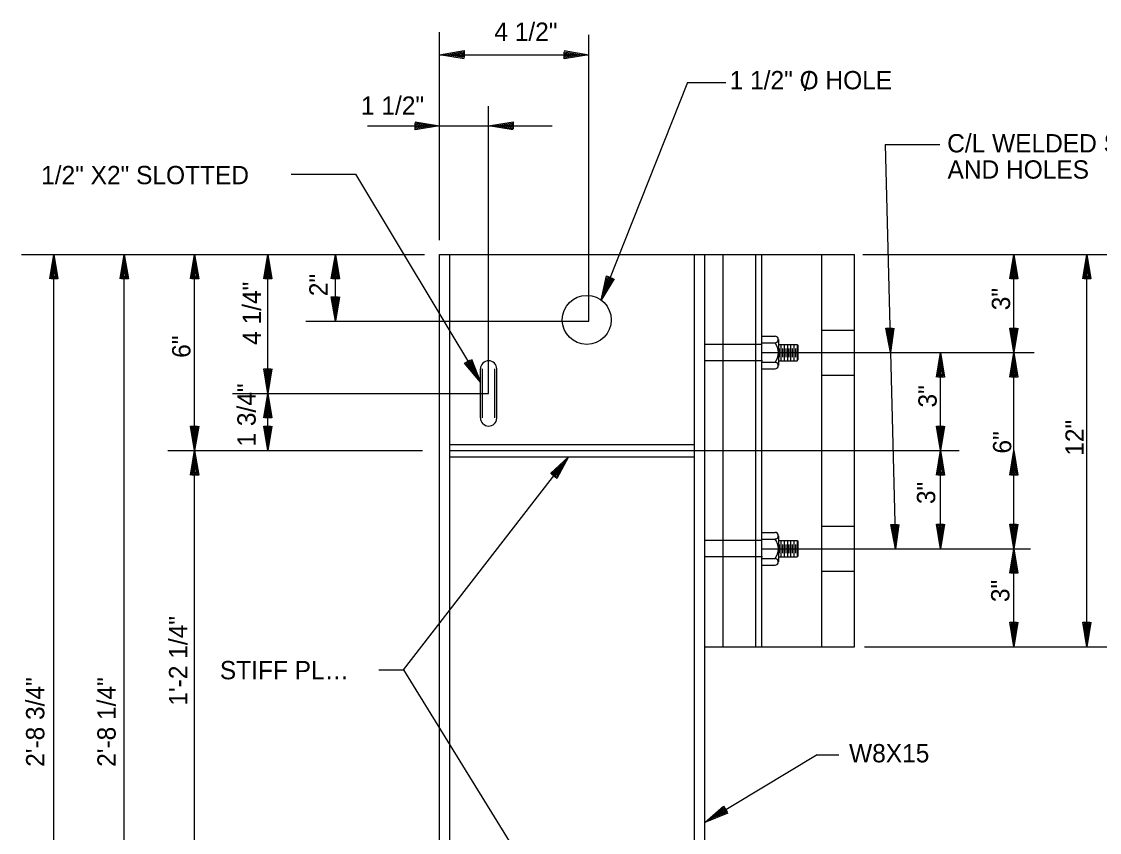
# Model space of a CAD drawing. Extents: x 0.1 to 13.5, y 0.1 to 9.5.
# Drawn here: x 9.259 to 12.007, y 5.002 to 7.069 of the extents above; entities that cross this region are included whole.
import ezdxf

# ---------------------------------------------------------------- set-up
doc = ezdxf.new("R2010")
doc.units = 0
for name, color, linetype in [('Level 13', 7, 'Continuous'), ('Level 25', 7, 'Continuous'), ('Level 50', 7, 'Continuous')]:
    doc.layers.add(name, color=color, linetype=linetype)

msp = doc.modelspace()

# ---------------------------------------------------------------- linework, layer by layer
at = {"layer": 'Level 13'}
for p, q in [((11.1464, 6.2666), (11.1797, 6.2666)), ((11.1469, 6.2457), (11.0006, 6.2457)), ((11.1464, 6.2494), (11.1797, 6.2494)), ((11.1881, 6.2581), (11.1881, 6.1916)), ((11.1881, 6.2457), (11.2359, 6.2457)), ((11.1944, 6.2457), (11.1944, 6.2041)), ((11.2027, 6.2457), (11.2027, 6.2041)), ((11.211, 6.2457), (11.211, 6.2041)), ((11.2194, 6.2457), (11.2194, 6.2041)), ((11.2277, 6.2457), (11.2277, 6.2041)), ((11.2359, 6.2457), (11.2381, 6.2435)), ((11.236, 6.2457), (11.236, 6.2041)), ((11.2381, 6.2435), (11.2381, 6.2062)), ((11.1902, 6.2353), (11.1902, 6.2135)), ((11.1985, 6.2353), (11.1985, 6.2135)), ((11.2069, 6.2353), (11.2069, 6.2135)), ((11.2152, 6.2353), (11.2152, 6.2135)), ((11.2235, 6.2353), (11.2235, 6.2135)), ((11.2319, 6.2353), (11.2319, 6.2135)), ((11.1476, 6.2041), (11.0006, 6.2041)), ((11.1464, 6.2001), (11.1797, 6.2001)), ((11.1464, 6.1832), (11.1797, 6.1832)), ((11.1881, 6.2041), (11.2358, 6.2041)), ((11.2358, 6.2041), (11.2381, 6.2062)), ((11.1469, 5.7457), (11.0006, 5.7457)), ((11.1464, 5.7666), (11.1797, 5.7666)), ((11.1464, 5.7494), (11.1797, 5.7494)), ((11.1881, 5.7581), (11.1881, 5.6916)), ((11.1881, 5.7457), (11.2359, 5.7457)), ((11.1944, 5.7457), (11.1944, 5.7041)), ((11.2027, 5.7457), (11.2027, 5.7041)), ((11.211, 5.7457), (11.211, 5.7041)), ((11.2194, 5.7457), (11.2194, 5.7041)), ((11.2277, 5.7457), (11.2277, 5.7041)), ((11.2359, 5.7457), (11.2381, 5.7435)), ((11.236, 5.7457), (11.236, 5.7041)), ((11.2381, 5.7435), (11.2381, 5.7062)), ((11.1902, 5.7353), (11.1902, 5.7135)), ((11.1985, 5.7353), (11.1985, 5.7135)), ((11.2069, 5.7353), (11.2069, 5.7135)), ((11.2152, 5.7353), (11.2152, 5.7135)), ((11.2235, 5.7353), (11.2235, 5.7135)), ((11.2319, 5.7353), (11.2319, 5.7135)), ((11.1476, 5.7041), (11.0006, 5.7041)), ((11.1464, 5.7001), (11.1797, 5.7001)), ((11.1881, 5.7041), (11.2358, 5.7041)), ((11.2358, 5.7041), (11.2381, 5.7062)), ((11.1464, 5.6832), (11.1797, 5.6832))]:
    msp.add_line(p, q, dxfattribs=at)
for centre, radius, start, end in [((11.1796, 6.2581), 0.00844, 270.5659, 89.4341), ((11.1475, 6.2247), 0.0406, 322.4343, 37.5657), ((11.1796, 6.1917), 0.00843, 270.4975, 89.5025), ((11.1796, 5.7581), 0.00844, 270.5659, 89.4341), ((11.1475, 5.7247), 0.0406, 322.4343, 37.5657), ((11.1796, 5.6917), 0.00843, 270.4975, 89.5025)]:
    msp.add_arc(centre, radius, start, end, dxfattribs=at)
at = {"layer": 'Level 25'}
for p, q in [((10.3247, 6.5117), (10.3247, 7.0417)), ((10.7048, 6.3047), (10.7048, 7.0348)), ((10.3247, 6.9843), (10.7048, 6.9843)), ((10.9565, 6.9132), (10.7368, 6.3586)), ((10.9565, 6.9132), (11.0544, 6.9132)), ((10.4497, 6.4749), (10.4497, 6.8533)), ((10.1408, 6.8029), (10.3247, 6.8029)), ((10.3247, 6.8029), (10.4497, 6.8029)), ((10.4497, 6.8029), (10.6115, 6.8029)), ((11.4602, 6.755), (11.6001, 6.755)), ((11.4602, 6.755), (11.4737, 6.2249)), ((9.9466, 6.6798), (10.1099, 6.6798)), ((10.1099, 6.6798), (10.4289, 6.1497)), ((9.2591, 6.4749), (10.2858, 6.4749)), ((9.3416, 3.7457), (9.3416, 6.4749)), ((9.5209, 3.7874), (9.5209, 6.4749)), ((9.7003, 5.9749), (9.7003, 6.4749)), ((9.8869, 6.1207), (9.8869, 6.4749)), ((10.059, 6.3047), (10.059, 6.4749)), ((10.3247, 6.4749), (11.382, 6.4749)), ((10.3247, 6.4749), (10.3247, 6.4749)), ((10.3247, 3.7457), (10.3247, 6.4749)), ((10.351, 3.8291), (10.351, 6.4749)), ((10.4497, 6.1207), (10.4497, 6.4749)), ((10.9743, 3.8291), (10.9743, 6.4749)), ((11.0006, 3.7457), (11.0006, 6.4749)), ((11.0474, 5.4749), (11.0474, 6.4749)), ((11.1308, 5.4749), (11.1308, 6.4749)), ((11.1464, 5.4749), (11.1464, 6.4749)), ((11.2987, 5.4749), (11.2987, 6.4749)), ((11.382, 5.4749), (11.382, 6.4749)), ((11.4035, 6.4749), (12.0554, 6.4749)), ((11.7881, 6.2249), (11.7881, 6.4749)), ((11.9747, 5.4749), (11.9747, 6.4749)), ((9.9838, 6.3047), (10.7048, 6.3047)), ((11.1464, 6.1832), (11.1464, 6.2666)), ((11.2987, 6.2822), (11.382, 6.2822)), ((11.1464, 6.2249), (11.84, 6.2249)), ((11.4737, 6.2249), (11.4864, 5.7243)), ((11.6016, 5.9749), (11.6016, 6.2249)), ((11.7881, 5.7249), (11.7881, 6.2249)), ((10.4289, 6.0582), (10.4289, 6.1832)), ((10.4341, 6.0582), (10.4341, 6.1832)), ((10.4654, 6.0582), (10.4654, 6.1832)), ((10.4706, 6.0582), (10.4706, 6.1832)), ((11.2987, 6.1676), (11.382, 6.1676)), ((9.7972, 6.1207), (10.4497, 6.1207)), ((9.8869, 5.9749), (9.8869, 6.1207)), ((10.351, 5.9905), (10.9743, 5.9905)), ((9.6322, 5.9749), (10.2811, 5.9749)), ((9.7003, 4.7874), (9.7003, 5.9749)), ((10.351, 5.9749), (10.9743, 5.9749)), ((10.9743, 5.9749), (11.6492, 5.9749)), ((11.6016, 5.7249), (11.6016, 5.9749)), ((10.2325, 5.4159), (10.6535, 5.9593)), ((10.351, 5.9593), (10.9743, 5.9593)), ((11.2987, 5.7822), (11.382, 5.7822)), ((11.1464, 5.6832), (11.1464, 5.7666)), ((11.1464, 5.7249), (11.8311, 5.7249)), ((11.7881, 5.4749), (11.7881, 5.7249)), ((11.2987, 5.6676), (11.382, 5.6676)), ((11.0006, 5.4749), (11.382, 5.4749)), ((11.4081, 5.4749), (12.0554, 5.4749)), ((10.1696, 5.4159), (10.2325, 5.4159)), ((10.2325, 5.4159), (10.6112, 4.803)), ((11.2871, 5.199), (11.0006, 5.0273)), ((11.2871, 5.199), (11.3424, 5.199))]:
    msp.add_line(p, q, dxfattribs=at)
msp.add_circle((10.6997, 6.3082), 0.0625, dxfattribs=at)
for centre, start, end in [((10.4497, 6.1832), 0, 180), ((10.4497, 6.0582), 180, 357.4819)]:
    msp.add_arc(centre, 0.0208, start, end, dxfattribs=at)
at = {"layer": 'Level 50'}
for p, q in [((10.3247, 6.9843), (10.3247, 6.9843)), ((10.3421, 6.9843), (10.3421, 6.9843)), ((10.6875, 6.9843), (10.6875, 6.9843)), ((10.7048, 6.9843), (10.7048, 6.9843)), ((10.3074, 6.8029), (10.3074, 6.8029)), ((10.3247, 6.8029), (10.3247, 6.8029)), ((10.4497, 6.8029), (10.4497, 6.8029)), ((10.4671, 6.8029), (10.4671, 6.8029)), ((9.3416, 6.4749), (9.3416, 6.4749)), ((9.3416, 6.4576), (9.3416, 6.4576)), ((9.5209, 6.4749), (9.5209, 6.4749)), ((9.5209, 6.4576), (9.5209, 6.4576)), ((9.7003, 6.4749), (9.7003, 6.4749)), ((9.7003, 6.4576), (9.7003, 6.4576)), ((9.8869, 6.4749), (9.8869, 6.4749)), ((9.8869, 6.4576), (9.8869, 6.4576)), ((10.059, 6.4749), (10.059, 6.4749)), ((10.059, 6.4576), (10.059, 6.4576)), ((11.7881, 6.4749), (11.7881, 6.4749)), ((11.7881, 6.4576), (11.7881, 6.4576)), ((11.9747, 6.4749), (11.9747, 6.4749)), ((11.9747, 6.4576), (11.9747, 6.4576)), ((10.7432, 6.3747), (10.7432, 6.3747)), ((10.7368, 6.3586), (10.7368, 6.3586)), ((10.059, 6.322), (10.059, 6.322)), ((10.059, 6.3047), (10.059, 6.3047)), ((11.4733, 6.2422), (11.4733, 6.2422)), ((11.7881, 6.2422), (11.7881, 6.2422)), ((11.4737, 6.2249), (11.4737, 6.2249)), ((11.6016, 6.2249), (11.6016, 6.2249)), ((11.7881, 6.2249), (11.7881, 6.2249)), ((11.7881, 6.2249), (11.7881, 6.2249)), ((11.6016, 6.2076), (11.6016, 6.2076)), ((11.7881, 6.2076), (11.7881, 6.2076)), ((10.42, 6.1645), (10.42, 6.1645)), ((9.8869, 6.1381), (9.8869, 6.1381)), ((10.4289, 6.1497), (10.4289, 6.1497)), ((9.8869, 6.1207), (9.8869, 6.1207)), ((9.8869, 6.1207), (9.8869, 6.1207)), ((9.8869, 6.1034), (9.8869, 6.1034)), ((9.7003, 5.9922), (9.7003, 5.9922)), ((9.8869, 5.9922), (9.8869, 5.9922)), ((11.6016, 5.9922), (11.6016, 5.9922)), ((9.7003, 5.9749), (9.7003, 5.9749)), ((9.7003, 5.9749), (9.7003, 5.9749)), ((9.8869, 5.9749), (9.8869, 5.9749)), ((11.6016, 5.9749), (11.6016, 5.9749)), ((11.6016, 5.9749), (11.6016, 5.9749)), ((11.7881, 5.9749), (11.7881, 5.9749)), ((9.7003, 5.9576), (9.7003, 5.9576)), ((10.6428, 5.9456), (10.6428, 5.9456)), ((10.6428, 5.9456), (10.6428, 5.9456)), ((10.6535, 5.9593), (10.6535, 5.9593)), ((10.6535, 5.9593), (10.6535, 5.9593)), ((11.6016, 5.9576), (11.6016, 5.9576)), ((11.7881, 5.9576), (11.7881, 5.9576)), ((11.6016, 5.7422), (11.6016, 5.7422)), ((11.7881, 5.7422), (11.7881, 5.7422)), ((11.486, 5.7416), (11.486, 5.7416)), ((11.4864, 5.7243), (11.4864, 5.7243)), ((11.6016, 5.7249), (11.6016, 5.7249)), ((11.7881, 5.7249), (11.7881, 5.7249)), ((11.7881, 5.7249), (11.7881, 5.7249)), ((11.7881, 5.7076), (11.7881, 5.7076)), ((11.7881, 5.4922), (11.7881, 5.4922)), ((11.7881, 5.4749), (11.7881, 5.4749)), ((11.9747, 5.4922), (11.9747, 5.4922)), ((11.9747, 5.4749), (11.9747, 5.4749)), ((11.0154, 5.0362), (11.0154, 5.0362)), ((11.0006, 5.0273), (11.0006, 5.0273))]:
    msp.add_line(p, q, dxfattribs=at)
for points in [[(10.3871, 6.974), (10.3247, 6.9843), (10.3871, 6.9946), (10.3871, 6.977), (10.3421, 6.9843), (10.3844, 6.9913), (10.3844, 6.98), (10.3587, 6.9843), (10.3817, 6.988), (10.3817, 6.9833), (10.3761, 6.9843)], [(10.6425, 6.9946), (10.7048, 6.9843), (10.6425, 6.974), (10.6425, 6.9916), (10.6875, 6.9843), (10.6451, 6.9773), (10.6451, 6.9886), (10.6708, 6.9843), (10.6478, 6.9806), (10.6478, 6.9853), (10.6535, 6.9843)], [(10.2624, 6.8132), (10.3247, 6.8029), (10.2624, 6.7925), (10.2624, 6.8102), (10.3074, 6.8029), (10.2651, 6.7959), (10.2651, 6.8072), (10.2907, 6.8029), (10.2677, 6.7992), (10.2677, 6.8039), (10.2734, 6.8029)], [(10.5121, 6.7925), (10.4497, 6.8029), (10.5121, 6.8132), (10.5121, 6.7955), (10.4671, 6.8029), (10.5094, 6.8099), (10.5094, 6.7985), (10.4837, 6.8029), (10.5067, 6.8065), (10.5067, 6.8019), (10.5011, 6.8029)], [(9.3313, 6.4126), (9.3416, 6.4749), (9.3519, 6.4126), (9.3343, 6.4126), (9.3416, 6.4576), (9.3486, 6.4152), (9.3373, 6.4152), (9.3416, 6.4409), (9.3453, 6.4179), (9.3406, 6.4179), (9.3416, 6.4236)], [(9.5106, 6.4126), (9.5209, 6.4749), (9.5313, 6.4126), (9.5136, 6.4126), (9.5209, 6.4576), (9.5279, 6.4152), (9.5166, 6.4152), (9.5209, 6.4409), (9.5246, 6.4179), (9.5199, 6.4179), (9.5209, 6.4236)], [(9.69, 6.4126), (9.7003, 6.4749), (9.7106, 6.4126), (9.693, 6.4126), (9.7003, 6.4576), (9.7073, 6.4152), (9.696, 6.4152), (9.7003, 6.4409), (9.704, 6.4179), (9.6993, 6.4179), (9.7003, 6.4236)], [(9.8765, 6.4126), (9.8869, 6.4749), (9.8972, 6.4126), (9.8795, 6.4126), (9.8869, 6.4576), (9.8939, 6.4152), (9.8825, 6.4152), (9.8869, 6.4409), (9.8905, 6.4179), (9.8859, 6.4179), (9.8869, 6.4236)], [(10.0487, 6.4126), (10.059, 6.4749), (10.0694, 6.4126), (10.0517, 6.4126), (10.059, 6.4576), (10.066, 6.4152), (10.0547, 6.4152), (10.059, 6.4409), (10.0627, 6.4179), (10.058, 6.4179), (10.059, 6.4236)], [(11.7778, 6.4126), (11.7881, 6.4749), (11.7984, 6.4126), (11.7808, 6.4126), (11.7881, 6.4576), (11.7951, 6.4152), (11.7838, 6.4152), (11.7881, 6.4409), (11.7918, 6.4179), (11.7871, 6.4179), (11.7881, 6.4236)], [(11.9643, 6.4126), (11.9747, 6.4749), (11.985, 6.4126), (11.9673, 6.4126), (11.9747, 6.4576), (11.9817, 6.4152), (11.9703, 6.4152), (11.9747, 6.4409), (11.9783, 6.4179), (11.9737, 6.4179), (11.9747, 6.4236)], [(10.7694, 6.4127), (10.7368, 6.3586), (10.7502, 6.4203), (10.7666, 6.4138), (10.7432, 6.3747), (10.7523, 6.4166), (10.7628, 6.4124), (10.7493, 6.3902), (10.7544, 6.4129), (10.7587, 6.4112), (10.7557, 6.4063)], [(10.0694, 6.367), (10.059, 6.3047), (10.0487, 6.367), (10.0664, 6.367), (10.059, 6.322), (10.052, 6.3644), (10.0634, 6.3644), (10.059, 6.3387), (10.0554, 6.3617), (10.06, 6.3617), (10.059, 6.356)], [(11.4824, 6.2875), (11.4737, 6.2249), (11.4618, 6.287), (11.4794, 6.2874), (11.4733, 6.2422), (11.4652, 6.2844), (11.4765, 6.2847), (11.4728, 6.2589), (11.4686, 6.2818), (11.4732, 6.2819), (11.4724, 6.2762)], [(11.7984, 6.2872), (11.7881, 6.2249), (11.7778, 6.2872), (11.7954, 6.2872), (11.7881, 6.2422), (11.7811, 6.2846), (11.7924, 6.2846), (11.7881, 6.2589), (11.7844, 6.2819), (11.7891, 6.2819), (11.7881, 6.2762)], [(11.5913, 6.1626), (11.6016, 6.2249), (11.6119, 6.1626), (11.5943, 6.1626), (11.6016, 6.2076), (11.6086, 6.1652), (11.5973, 6.1652), (11.6016, 6.1909), (11.6053, 6.1679), (11.6006, 6.1679), (11.6016, 6.1736)], [(11.7778, 6.1626), (11.7881, 6.2249), (11.7984, 6.1626), (11.7808, 6.1626), (11.7881, 6.2076), (11.7951, 6.1652), (11.7838, 6.1652), (11.7881, 6.1909), (11.7918, 6.1679), (11.7871, 6.1679), (11.7881, 6.1736)], [(9.8972, 6.1831), (9.8869, 6.1207), (9.8765, 6.1831), (9.8942, 6.1831), (9.8869, 6.1381), (9.8799, 6.1804), (9.8912, 6.1804), (9.8869, 6.1547), (9.8832, 6.1777), (9.8879, 6.1777), (9.8869, 6.1721)], [(10.4056, 6.2084), (10.4289, 6.1497), (10.3879, 6.1977), (10.4031, 6.2068), (10.42, 6.1645), (10.3921, 6.1972), (10.4019, 6.203), (10.4114, 6.1788), (10.3964, 6.1966), (10.4004, 6.199), (10.4024, 6.1936)], [(9.8765, 6.0584), (9.8869, 6.1207), (9.8972, 6.0584), (9.8795, 6.0584), (9.8869, 6.1034), (9.8939, 6.0611), (9.8825, 6.0611), (9.8869, 6.0867), (9.8905, 6.0637), (9.8859, 6.0637), (9.8869, 6.0694)], [(9.7106, 6.0372), (9.7003, 5.9749), (9.69, 6.0372), (9.7076, 6.0372), (9.7003, 5.9922), (9.6933, 6.0346), (9.7046, 6.0346), (9.7003, 6.0089), (9.6966, 6.0319), (9.7013, 6.0319), (9.7003, 6.0262)], [(9.8972, 6.0372), (9.8869, 5.9749), (9.8765, 6.0372), (9.8942, 6.0372), (9.8869, 5.9922), (9.8799, 6.0346), (9.8912, 6.0346), (9.8869, 6.0089), (9.8832, 6.0319), (9.8879, 6.0319), (9.8869, 6.0262)], [(11.6119, 6.0372), (11.6016, 5.9749), (11.5913, 6.0372), (11.6089, 6.0372), (11.6016, 5.9922), (11.5946, 6.0346), (11.6059, 6.0346), (11.6016, 6.0089), (11.5979, 6.0319), (11.6026, 6.0319), (11.6016, 6.0262)], [(9.69, 5.9126), (9.7003, 5.9749), (9.7106, 5.9126), (9.693, 5.9126), (9.7003, 5.9576), (9.7073, 5.9152), (9.696, 5.9152), (9.7003, 5.9409), (9.704, 5.9179), (9.6993, 5.9179), (9.7003, 5.9236)], [(11.5913, 5.9126), (11.6016, 5.9749), (11.6119, 5.9126), (11.5943, 5.9126), (11.6016, 5.9576), (11.6086, 5.9152), (11.5973, 5.9152), (11.6016, 5.9409), (11.6053, 5.9179), (11.6006, 5.9179), (11.6016, 5.9236)], [(11.7778, 5.9126), (11.7881, 5.9749), (11.7984, 5.9126), (11.7808, 5.9126), (11.7881, 5.9576), (11.7951, 5.9152), (11.7838, 5.9152), (11.7881, 5.9409), (11.7918, 5.9179), (11.7871, 5.9179), (11.7881, 5.9236)], [(10.6071, 5.9163), (10.6535, 5.9593), (10.6235, 5.9037), (10.6095, 5.9145), (10.6428, 5.9456), (10.6224, 5.9078), (10.6135, 5.9148), (10.6326, 5.9324), (10.6214, 5.912), (10.6178, 5.9148), (10.622, 5.9187)], [(10.6071, 5.9163), (10.6535, 5.9593), (10.6235, 5.9037), (10.6095, 5.9145), (10.6428, 5.9456), (10.6224, 5.9078), (10.6135, 5.9148), (10.6326, 5.9324), (10.6214, 5.912), (10.6178, 5.9148), (10.622, 5.9187)], [(11.4952, 5.7868), (11.4864, 5.7243), (11.4745, 5.7863), (11.4922, 5.7868), (11.486, 5.7416), (11.4779, 5.7837), (11.4892, 5.784), (11.4856, 5.7583), (11.4813, 5.7812), (11.486, 5.7813), (11.4851, 5.7756)], [(11.6119, 5.7872), (11.6016, 5.7249), (11.5913, 5.7872), (11.6089, 5.7872), (11.6016, 5.7422), (11.5946, 5.7846), (11.6059, 5.7846), (11.6016, 5.7589), (11.5979, 5.7819), (11.6026, 5.7819), (11.6016, 5.7762)], [(11.7984, 5.7872), (11.7881, 5.7249), (11.7778, 5.7872), (11.7954, 5.7872), (11.7881, 5.7422), (11.7811, 5.7846), (11.7924, 5.7846), (11.7881, 5.7589), (11.7844, 5.7819), (11.7891, 5.7819), (11.7881, 5.7762)], [(11.7778, 5.6626), (11.7881, 5.7249), (11.7984, 5.6626), (11.7808, 5.6626), (11.7881, 5.7076), (11.7951, 5.6652), (11.7838, 5.6652), (11.7881, 5.6909), (11.7918, 5.6679), (11.7871, 5.6679), (11.7881, 5.6736)], [(11.7984, 5.5372), (11.7881, 5.4749), (11.7778, 5.5372), (11.7954, 5.5372), (11.7881, 5.4922), (11.7811, 5.5346), (11.7924, 5.5346), (11.7881, 5.5089), (11.7844, 5.5319), (11.7891, 5.5319), (11.7881, 5.5262)], [(11.985, 5.5372), (11.9747, 5.4749), (11.9643, 5.5372), (11.982, 5.5372), (11.9747, 5.4922), (11.9677, 5.5346), (11.979, 5.5346), (11.9747, 5.5089), (11.971, 5.5319), (11.9757, 5.5319), (11.9747, 5.5262)], [(11.0594, 5.0505), (11.0006, 5.0273), (11.0487, 5.0682), (11.0578, 5.0531), (11.0154, 5.0362), (11.0482, 5.064), (11.054, 5.0543), (11.0297, 5.0448), (11.0476, 5.0598), (11.05, 5.0558), (11.0446, 5.0537)]]:
    msp.add_lwpolyline(points, dxfattribs=at)

# ---------------------------------------------------------------- texts
at = {"layer": 'Level 25'}
for s, height, p in [('4 1/2"', 0.04667, (10.4642, 7.0196)), ('1 1/2" O HOLE', 0.046667, (11.064, 6.8961)), ('/', 0.0467, (11.2531, 6.8925)), ('1 1/2"', 0.04667, (10.1242, 6.8312)), ('C/L WELDED STUDS', 0.046667, (11.6184, 6.7352)), ('AND HOLES', 0.04667, (11.6193, 6.6683)), ('1/2" X2" SLOTTED', 0.046667, (9.309, 6.6541)), ('STIFF PL…', 0.04667, (9.7646, 5.392)), ('W8X15', 0.04667, (11.3683, 5.1802))]:
    msp.add_text(s, height=height, dxfattribs=at).set_placement(p)
for s, p in [('4 1/4"', (9.8694, 6.2446)), ('2"', (10.0392, 6.3687)), ('3"', (11.7788, 6.3328)), ('6"', (9.6896, 6.2115)), ('1 3/4"', (9.8558, 5.9853)), ('3"', (11.5916, 6.0848)), ('12"', (11.9665, 5.9619)), ('6"', (11.7818, 5.9675)), ('3"', (11.588, 5.8386)), ('3"', (11.777, 5.5888)), ('1\'-2 1/4"', (9.6815, 5.3249)), ('2\'-8 3/4"', (9.3172, 5.1688)), ('2\'-8 1/4"', (9.499, 5.1688))]:
    msp.add_text(s, height=0.04667, rotation=90, dxfattribs=at).set_placement(p)

doc.saveas('drawing.dxf')
